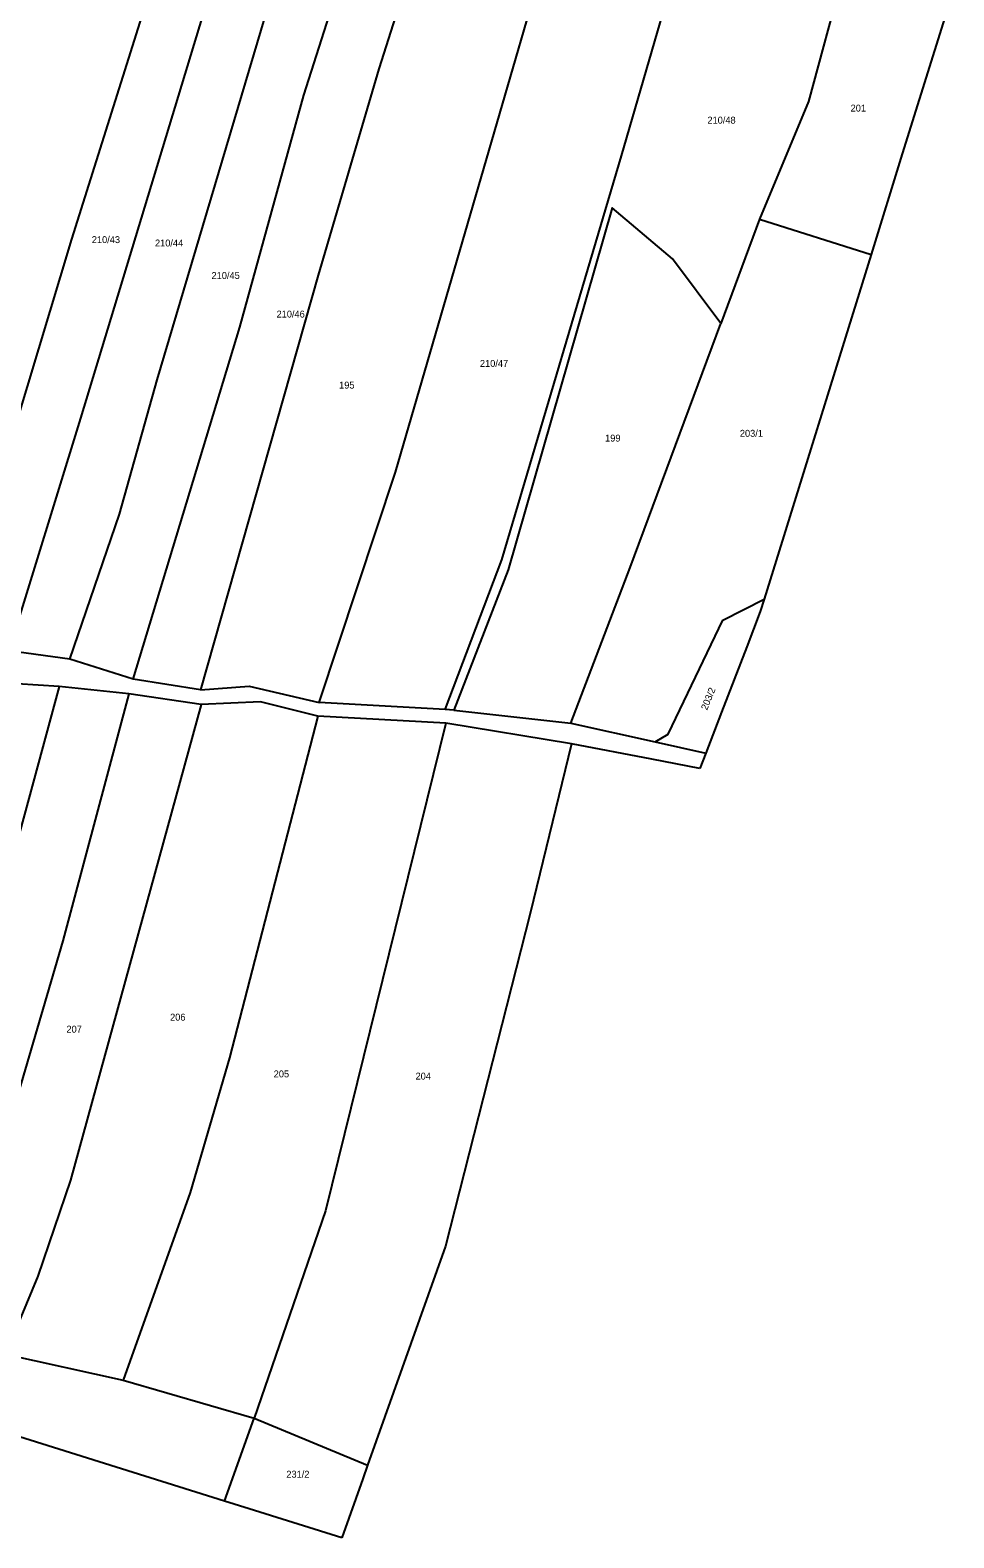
# Model space of a CAD drawing. Extents: x -746176 to -739709, y -1128407 to -1124482.
# Drawn here: x -742474.2 to -742246.8, y -1127907.2 to -1127536.1 of the extents above; entities that cross this region are included whole.
import ezdxf

# ---------------------------------------------------------------- set-up
doc = ezdxf.new("R2010")
doc.units = 0
doc.layers.add('Hranice parcel', color=7, linetype='Continuous')
doc.layers.add('Parcelní čísla', color=7, linetype='Continuous')

msp = doc.modelspace()

# ---------------------------------------------------------------- linework, layer by layer
at = {"layer": 'Hranice parcel'}
for p, q in [((-742246.84, -1127525.71), (-742259.53, -1127566.57)), ((-742259.53, -1127566.57), (-742267.21, -1127591.32)), ((-742294.71, -1127582.66), (-742304.21, -1127608.28)), ((-742294.71, -1127582.66), (-742267.21, -1127591.32)), ((-742267.21, -1127591.32), (-742293.55, -1127676.19)), ((-742293.55, -1127676.19), (-742294.48, -1127679.19)), ((-742294.48, -1127679.19), (-742297.82, -1127687.89)), ((-742464.41, -1127690.97), (-742479.32, -1127688.85)), ((-742448.8, -1127695.84), (-742464.41, -1127690.97)), ((-742297.82, -1127687.89), (-742304, -1127703.97)), ((-742467.04, -1127697.67), (-742483.38, -1127696.63)), ((-742449.94, -1127699.44), (-742467.04, -1127697.67)), ((-742432.3, -1127698.48), (-742448.8, -1127695.84)), ((-742432.12, -1127702.08), (-742449.94, -1127699.44)), ((-742372.01, -1127703.32), (-742403.02, -1127701.6)), ((-742371.88, -1127706.65), (-742403.42, -1127704.93)), ((-742369.9, -1127703.45), (-742372.01, -1127703.32)), ((-742369.9, -1127703.45), (-742341.09, -1127706.66)), ((-742304, -1127703.97), (-742307.87, -1127714.04)), ((-742340.92, -1127711.81), (-742371.88, -1127706.65)), ((-742341.09, -1127706.66), (-742320.38, -1127711.26)), ((-742321.14, -1127715.58), (-742340.92, -1127711.81)), ((-742320.38, -1127711.26), (-742307.87, -1127714.04)), ((-742309.33, -1127717.84), (-742321.14, -1127715.58)), ((-742307.87, -1127714.04), (-742309.33, -1127717.84)), ((-742480.24, -1127862.01), (-742451.26, -1127868.39)), ((-742451.26, -1127868.39), (-742419.07, -1127877.77)), ((-742426.38, -1127898.15), (-742491.5, -1127877.75)), ((-742426.38, -1127898.15), (-742419.07, -1127877.77)), ((-742419.07, -1127877.77), (-742391.12, -1127889.33)), ((-742391.12, -1127889.33), (-742392.3, -1127892.65)), ((-742392.3, -1127892.65), (-742397.46, -1127907.21)), ((-742420.31, -1127900.05), (-742426.38, -1127898.15)), ((-742397.46, -1127907.21), (-742420.31, -1127900.05))]:
    msp.add_line(p, q, dxfattribs=at)
for points in [[(-742494, -1127687.08), (-742463.97, -1127587.54), (-742428.89, -1127476.24)], [(-742479.32, -1127688.85), (-742461.68, -1127631.58), (-742415.87, -1127480.36)], [(-742464.41, -1127690.97), (-742452.19, -1127655.25), (-742442.95, -1127622.18), (-742402.15, -1127485.01)], [(-742448.8, -1127695.84), (-742422.61, -1127609.18), (-742406.86, -1127552.13), (-742387.37, -1127491.14)], [(-742373.12, -1127497.63), (-742388.36, -1127545.64), (-742403.33, -1127596.39), (-742432.3, -1127698.48)], [(-742403.02, -1127701.6), (-742384.25, -1127644.88), (-742343.44, -1127504.37)], [(-742372.01, -1127703.32), (-742358.1, -1127666.45), (-742328.66, -1127567.04), (-742312.99, -1127513.08), (-742313.1, -1127510.34)], [(-742274.2, -1127522.4), (-742282.6, -1127553.63), (-742294.71, -1127582.66)], [(-742304.21, -1127608.28), (-742316.12, -1127592.36), (-742330.9, -1127579.81), (-742356.55, -1127668.96), (-742369.9, -1127703.45)], [(-742341.09, -1127706.66), (-742326.47, -1127668.34), (-742304.21, -1127608.28)], [(-742320.38, -1127711.26), (-742317.14, -1127709.37), (-742303.66, -1127681.35), (-742293.55, -1127676.19)], [(-742467.04, -1127697.67), (-742480.9, -1127748.82), (-742494.32, -1127803.6), (-742511.96, -1127847.84)], [(-742432.3, -1127698.48), (-742420.3, -1127697.56), (-742403.02, -1127701.6)], [(-742449.94, -1127699.44), (-742466.13, -1127760.26), (-742485.77, -1127826.93), (-742498.72, -1127857.52)], [(-742432.12, -1127702.08), (-742464.27, -1127819.17), (-742472.32, -1127842.8), (-742480.24, -1127862.01)], [(-742403.42, -1127704.93), (-742417.48, -1127701.42), (-742432.12, -1127702.08)], [(-742403.42, -1127704.93), (-742425.12, -1127789.08), (-742434.82, -1127822.21), (-742451.26, -1127868.39)], [(-742371.88, -1127706.65), (-742401.48, -1127826.73), (-742419.07, -1127877.77)], [(-742340.92, -1127711.81), (-742351.14, -1127753.54), (-742371.99, -1127835.4), (-742391.12, -1127889.33)]]:
    msp.add_lwpolyline(points, dxfattribs=at)

# ---------------------------------------------------------------- texts
at = {"layer": 'Parcelní čísla'}
for s, p in [('210/48', (-742307.5, -1127559.11)), ('201', (-742272.25, -1127556.14)), ('210/43', (-742459.02, -1127588.52)), ('210/44', (-742443.47, -1127589.35)), ('210/45', (-742429.55, -1127597.35)), ('210/46', (-742413.55, -1127606.84)), ('210/47', (-742363.49, -1127618.99)), ('195', (-742398.15, -1127624.33)), ('199', (-742332.68, -1127637.37)), ('203/1', (-742299.51, -1127636.19)), ('206', (-742439.75, -1127779.9)), ('207', (-742465.26, -1127782.86)), ('205', (-742414.25, -1127793.87)), ('204', (-742379.34, -1127794.41)), ('231/2', (-742411.14, -1127892.4))]:
    msp.add_text(s, height=1.7, dxfattribs=at).set_placement(p)
msp.add_text('203/2', height=1.7, rotation=68, dxfattribs=at).set_placement((-742307.58, -1127703.62))

doc.saveas('drawing.dxf')
